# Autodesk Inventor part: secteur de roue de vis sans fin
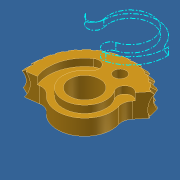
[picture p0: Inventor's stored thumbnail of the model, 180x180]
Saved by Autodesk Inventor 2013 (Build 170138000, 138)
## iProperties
Created: 2011-10
Part Number: secteur de roue de vis sans fin
Material: Laiton (jaune doux)
Document SubType Name: Modeling
Designer: Laur
Mass: 5.8954 g
Surface Area: 7.57262 cm^2
Volume: 0.696033 cm^3
Density: 8.47 g/cm^3
Author: Laur
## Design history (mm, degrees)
derived "secteur roue de vis sans fin.iam"
sketch "Esquisse2"
  geometry: L1 (-10.467, -29.707)-(10.078, 28.605) reference; L2 (-5.666, -0.387)-(-9.988, 0.485); L3 (5.478, 1.496)-(9.274, 3.74); A1 r 7.753 centre (0, 0) between (2.119, 7.458) and (1.097, 7.675) reference; A2 r 1.5 centre (0, 0) between (-0.498, -1.415) and (0.498, 1.415); A3 r 1.5 centre (0, 0) between (-0.297, -1.47) and (0.763, -1.291); A4 r 10 centre (0, 0) between (-9.988, 0.485) and (9.274, 3.74); A5 r 7.753 centre (0, 0) between (3.623, 6.854) and (2.669, 7.279) reference; A6 r 4.5 centre (0, 0) between (-4.196, -1.625) and (4.497, -0.156); A7 r 2 centre (-6.061, -2.347) between (-4.196, -1.625) and (-5.666, -0.387); A8 r 2 centre (6.496, -0.225) between (5.478, 1.496) and (4.497, -0.156)
  constraints: 14 point on circle, 7 tangent, 6 centre point, 4 coincident, 4 end point, 4 point on line, 1 equal radius
  dimensions: "d4" = 3 diameter of A2; "d5" = 138 deg angle of L3 L2; "d6" = 40 deg angle of L3 L1; "d7" = 10 radius of A4; "d10" = 4.5 radius of A6; "d11" = 2 radius of A7
extrude "découpe secteur 13 dents complètes" cut sketch "Esquisse2" stored distance "d8" = 10; taper "d9" = 0 deg
sketch "Esquisse3"
  geometry: L1 (1.443, 5.492)-(1.421, 7.622) reference; L2 (0, 0)-(-4.628, 8.15); C1 r 2.5 at (0, 0); C2 r 1 at (-2.469, 4.348); A1 r 7.753 centre (0, 0) between (1.421, 7.622) and (1.097, 7.675) reference; A2 r 7.753 centre (0, 0) between (-4.969, -5.951) and (-4.124, -6.565) reference
  constraints: 2 centre point, 2 end point, 1 coincident, 1 point on line
  dimensions: "d12" = 29 deg angle of L1 L2; "d13" = 2 diameter of C2; "d14" = 5 distance of A1.centre C2.centre; "d15" = 5 diameter of C1
extrude "alésage arbre et alésage capteur angulaire" cut sketch "Esquisse3" stored distance "d16" = 10; taper "d17" = 0 deg
sketch "Esquisse4"
  geometry: L1 (1.443, 5.492)-(1.421, 7.622) reference; L2 (0, 0)-(-0.074, 7.137); L3 (0, 0)-(-10.241, 5.772); A1 r 7.753 centre (0, 0) between (-4.969, -5.951) and (-4.124, -6.565) reference; A2 r 6 centre (0, 0) between (-5.808, 1.507) and (1.44, 5.825); A3 r 3.55 centre (0, 0) between (-3.436, 0.891) and (0.875, 3.44); A4 r 1.225 centre (-4.622, 1.199) between (-3.436, 0.891) and (-5.808, 1.507); A5 r 1.225 centre (1.177, 4.628) between (1.479, 5.815) and (0.875, 3.44)
  constraints: 9 point on circle, 6 tangent, 4 centre point, 4 end point, 2 coincident, 1 parallel, 1 point on line
  dimensions: "d18" = 60 deg angle of L2 L3; "d19" = 7.1 diameter of A3; "d21" = 12 diameter of A2
extrude "Extrusion3" cut sketch "Esquisse4" distance "d22" = 1.2; taper "d23" = 0 deg
sketch "Esquisse5"
  geometry: L1 (5.539, -1.251)-(7.667, -1.155) reference; L2 (-6.76, 3.613)-(-5.184, 2.318) reference; L3 (0, 0)-(4.908, 14.746); C1 r 2.5 at (0, 0) reference; C2 r 1 at (-1.84, 4.649) reference; A1 r 7.753 centre (0, 0) between (7.667, -1.155) and (7.675, -1.097) reference; A2 r 7.753 centre (0, 0) between (7.736, -0.522) and (7.736, 0.522) reference; A3 r 7.753 centre (0, 0) between (7.675, 1.097) and (7.458, 2.119) reference; A4 r 7.753 centre (0, 0) between (7.279, 2.669) and (6.854, 3.623) reference; A5 r 7.753 centre (0, 0) between (6.565, 4.124) and (5.951, 4.969) reference; A6 r 7.753 centre (0, 0) between (5.564, 5.399) and (4.788, 6.098) reference; A7 r 7.753 centre (0, 0) between (4.32, 6.438) and (3.415, 6.96) reference; A8 r 7.753 centre (0, 0) between (2.887, 7.195) and (1.894, 7.518) reference; A9 r 7.753 centre (0, 0) between (1.328, 7.639) and (0.289, 7.748) reference; A10 r 7.753 centre (0, 0) between (-0.289, 7.748) and (-1.328, 7.639) reference; A11 r 7.753 centre (0, 0) between (-1.894, 7.518) and (-2.887, 7.195) reference; A12 r 7.753 centre (0, 0) between (-3.415, 6.96) and (-4.32, 6.438) reference; A13 r 7.753 centre (0, 0) between (-4.788, 6.098) and (-5.564, 5.399) reference; A14 r 7.753 centre (0, 0) between (-5.951, 4.969) and (-6.565, 4.124) reference; A15 r 2 centre (-6.454, 0.773) between (-4.468, 0.535) and (-5.184, 2.318) reference; A16 r 4.5 centre (0, 0) between (-4.468, 0.535) and (3.898, -2.249) reference; A17 r 2 centre (5.63, -3.249) between (5.539, -1.251) and (3.898, -2.249) reference; 41 further points; 14 other entities
  constraints: 2 end point, 41 other
  dimensions: "d24" = 138 deg angle of L1 L2 (derived); "d25" = 69 deg angle of L1 L3 (= 0.5 x d24)
node "Solide1"
node "Corps solides"
node "Corps surfaciques"
node "secteur-roue de sortie.ipt:1" dims "d0" = 10
node "Engrenages à vis sans fin:1::Engrenage à vis sans fin:1" dims "d0" = 10
